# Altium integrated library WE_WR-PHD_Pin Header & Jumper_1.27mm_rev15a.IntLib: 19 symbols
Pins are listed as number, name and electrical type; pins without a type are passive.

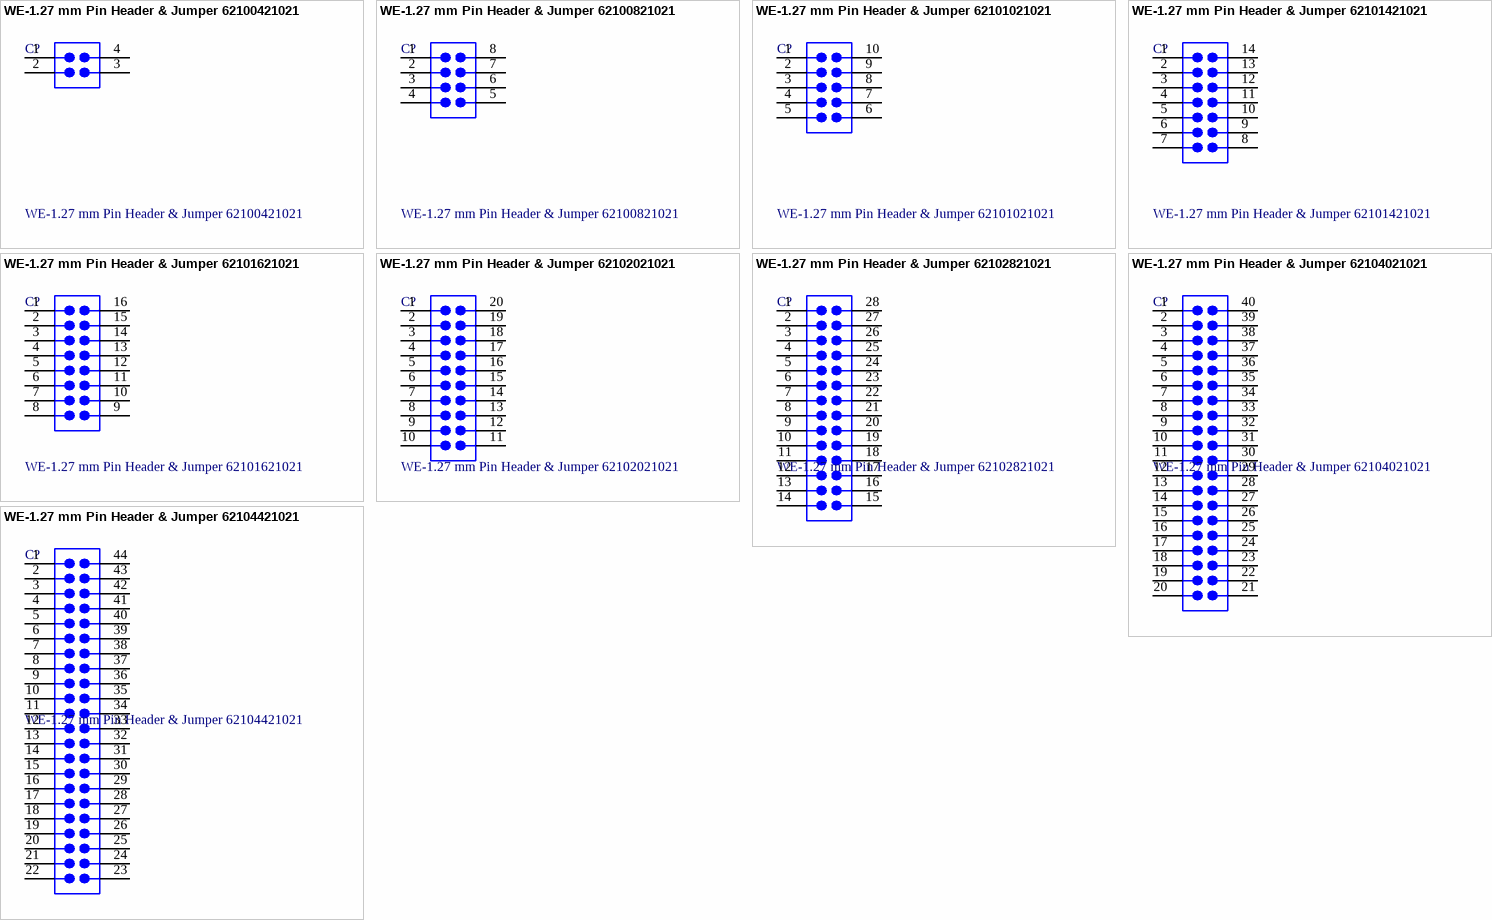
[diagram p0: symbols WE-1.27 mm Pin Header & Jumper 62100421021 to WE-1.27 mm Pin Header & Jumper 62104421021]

## WE-1.27 mm Pin Header & Jumper 62100421021
designator C?
WR-PHD 1.27 mm Dual SMT Pin Header; Manufacturer: Würth Elektronik eiSos GmbH; ComponentLink1 Description: Manufacturer; ComponentLink2 Description: Datasheet; NoPins: 04
footprint 62100421021 (4 pins, dual row, straight, gold plating)
pins: 1, 2, 3, 4

## WE-1.27 mm Pin Header & Jumper 62100821021
designator C?
WR-PHD 1.27 mm Dual SMT Pin Header; Manufacturer: Würth Elektronik eiSos GmbH; ComponentLink1 Description: Manufacturer; ComponentLink2 Description: Datasheet; NoPins: 08
footprint 62100821021 (8 pins, dual row, straight, gold plating)
pins: 1, 2, 3, 4, 5, 6, 7, 8

## WE-1.27 mm Pin Header & Jumper 62101021021
designator C?
WR-PHD 1.27 mm Dual SMT Pin Header; Manufacturer: Würth Elektronik eiSos GmbH; ComponentLink1 Description: Manufacturer; ComponentLink2 Description: Datasheet; NoPins: 10
footprint 62101021021 (10 pins, dual row, straight, gold plating)
pins: 1, 2, 3, 4, 5, 6, 7, 8, 9, 10

## WE-1.27 mm Pin Header & Jumper 62101421021
designator C?
WR-PHD 1.27 mm Dual SMT Pin Header; Manufacturer: Würth Elektronik eiSos GmbH; ComponentLink1 Description: Manufacturer; ComponentLink2 Description: Datasheet; NoPins: 14
footprint 62101421021 (14 pins, dual row, straight, gold plating)
pins: 1, 2, 3, 4, 5, 6, 7, 8, 9, 10, 11, 12, 13, 14

## WE-1.27 mm Pin Header & Jumper 62101621021
designator C?
WR-PHD 1.27 mm Dual SMT Pin Header; Manufacturer: Würth Elektronik eiSos GmbH; ComponentLink1 Description: Manufacturer; ComponentLink2 Description: Datasheet; NoPins: 16
footprint 62101621021 (16 pins, dual row, straight, gold plating)
pins: 1, 2, 3, 4, 5, 6, 7, 8, 9, 10, 11, 12, 13, 14, 15, 16

## WE-1.27 mm Pin Header & Jumper 62102021021
designator C?
WR-PHD 1.27 mm Dual SMT Pin Header; Manufacturer: Würth Elektronik eiSos GmbH; ComponentLink1 Description: Manufacturer; ComponentLink2 Description: Datasheet; NoPins: 20
footprint 62102021021 (20 pins, dual row, straight, gold plating)
pins: 1, 2, 3, 4, 5, 6, 7, 8, 9, 10, 11, 12, 13, 14, 15, 16, 17, 18, 19, 20

## WE-1.27 mm Pin Header & Jumper 62102821021
designator C?
WR-PHD 1.27 mm Dual SMT Pin Header; Manufacturer: Würth Elektronik eiSos GmbH; ComponentLink1 Description: Manufacturer; ComponentLink2 Description: Datasheet; NoPins: 28
footprint 62102821021 (28 pins, dual row, straight, gold plating)
pins: 1, 2, 3, 4, 5, 6, 7, 8, 9, 10, 11, 12, 13, 14, 15, 16, 17, 18, 19, 20, 21, 22, 23, 24, 25, 26, 27, 28

## WE-1.27 mm Pin Header & Jumper 62104021021
designator C?
WR-PHD 1.27 mm Dual SMT Pin Header; Manufacturer: Würth Elektronik eiSos GmbH; ComponentLink1 Description: Manufacturer; ComponentLink2 Description: Datasheet; NoPins: 40
footprint 62104021021 (40 pins, dual row, straight, gold plating)
pins: 1, 2, 3, 4, 5, 6, 7, 8, 9, 10, 11, 12, 13, 14, 15, 16, 17, 18, 19, 20, 21, 22, 23, 24, 25, 26, 27, 28, 29, 30, 31, 32, 33, 34, 35, 36, 37, 38, 39, 40

## WE-1.27 mm Pin Header & Jumper 62104421021
designator C?
WR-PHD 1.27 mm Dual SMT Pin Header; Manufacturer: Würth Elektronik eiSos GmbH; ComponentLink1 Description: Manufacturer; ComponentLink2 Description: Datasheet; NoPins: 44
footprint 62104421021 (44 pins, dual row, straight, gold plating)
pins: 1, 2, 3, 4, 5, 6, 7, 8, 9, 10, 11, 12, 13, 14, 15, 16, 17, 18, 19, 20, 21, 22, 23, 24, 25, 26, 27, 28, 29, 30, 31, 32, 33, 34, 35, 36, 37, 38, 39, 40, 41, 42, 43, 44


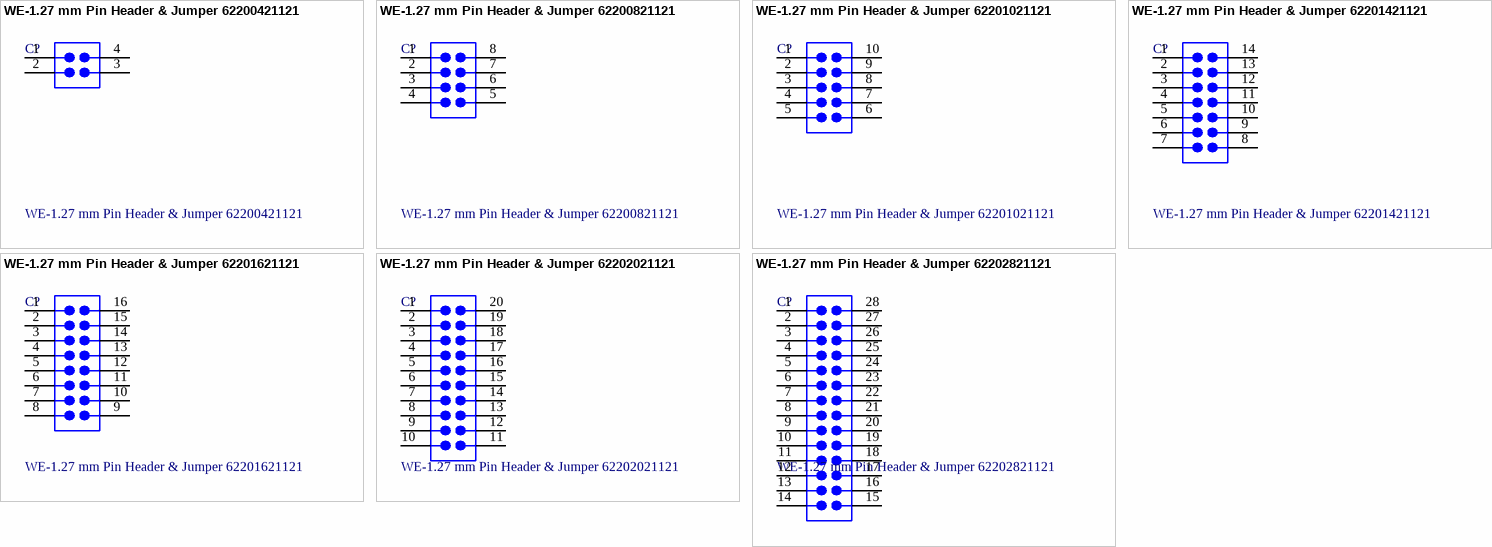
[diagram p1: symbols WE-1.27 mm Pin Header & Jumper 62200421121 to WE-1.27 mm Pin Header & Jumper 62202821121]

## WE-1.27 mm Pin Header & Jumper 62200421121
designator C?
WR-PHD 1.27 mm Dual Pin Header; Manufacturer: Würth Elektronik eiSos GmbH; ComponentLink1 Description: Manufacturer; ComponentLink2 Description: Datasheet; NoPins: 04
footprint 62200421121 (4 pins, dual row, straight, gold plating)
pins: 1, 2, 3, 4

## WE-1.27 mm Pin Header & Jumper 62200821121
designator C?
WR-PHD 1.27 mm Dual Pin Header; Manufacturer: Würth Elektronik eiSos GmbH; ComponentLink1 Description: Manufacturer; ComponentLink2 Description: Datasheet; NoPins: 08
footprint 62200821121 (8 pins, dual row, straight, gold plating)
pins: 1, 2, 3, 4, 5, 6, 7, 8

## WE-1.27 mm Pin Header & Jumper 62201021121
designator C?
WR-PHD 1.27 mm Dual Pin Header; Manufacturer: Würth Elektronik eiSos GmbH; ComponentLink1 Description: Manufacturer; ComponentLink2 Description: Datasheet; NoPins: 10
footprint 62201021121 (10 pins, dual row, straight, gold plating)
pins: 1, 2, 3, 4, 5, 6, 7, 8, 9, 10

## WE-1.27 mm Pin Header & Jumper 62201421121
designator C?
WR-PHD 1.27 mm Dual Pin Header; Manufacturer: Würth Elektronik eiSos GmbH; ComponentLink1 Description: Manufacturer; ComponentLink2 Description: Datasheet; NoPins: 10
footprint 62201421121 (14 pins, dual row, straight, gold plating)
pins: 1, 2, 3, 4, 5, 6, 7, 8, 9, 10, 11, 12, 13, 14

## WE-1.27 mm Pin Header & Jumper 62201621121
designator C?
WR-PHD 1.27 mm Dual Pin Header; Manufacturer: Würth Elektronik eiSos GmbH; ComponentLink1 Description: Manufacturer; ComponentLink2 Description: Datasheet; NoPins: 16
footprint 62201621121 (16 pins, dual row, straight, gold plating)
pins: 1, 2, 3, 4, 5, 6, 7, 8, 9, 10, 11, 12, 13, 14, 15, 16

## WE-1.27 mm Pin Header & Jumper 62202021121
designator C?
WR-PHD 1.27 mm Dual Pin Header; Manufacturer: Würth Elektronik eiSos GmbH; ComponentLink1 Description: Manufacturer; ComponentLink2 Description: Datasheet; NoPins: 20
footprint 62202021121 (20 pins, dual row, straight, gold plating)
pins: 1, 2, 3, 4, 5, 6, 7, 8, 9, 10, 11, 12, 13, 14, 15, 16, 17, 18, 19, 20

## WE-1.27 mm Pin Header & Jumper 62202821121
designator C?
WR-PHD 1.27 mm Dual Pin Header; Manufacturer: Würth Elektronik eiSos GmbH; ComponentLink1 Description: Manufacturer; ComponentLink2 Description: Datasheet; NoPins: 28
footprint 62202821121 (28 pins, dual row, straight, gold plating)
pins: 1, 2, 3, 4, 5, 6, 7, 8, 9, 10, 11, 12, 13, 14, 15, 16, 17, 18, 19, 20, 21, 22, 23, 24, 25, 26, 27, 28


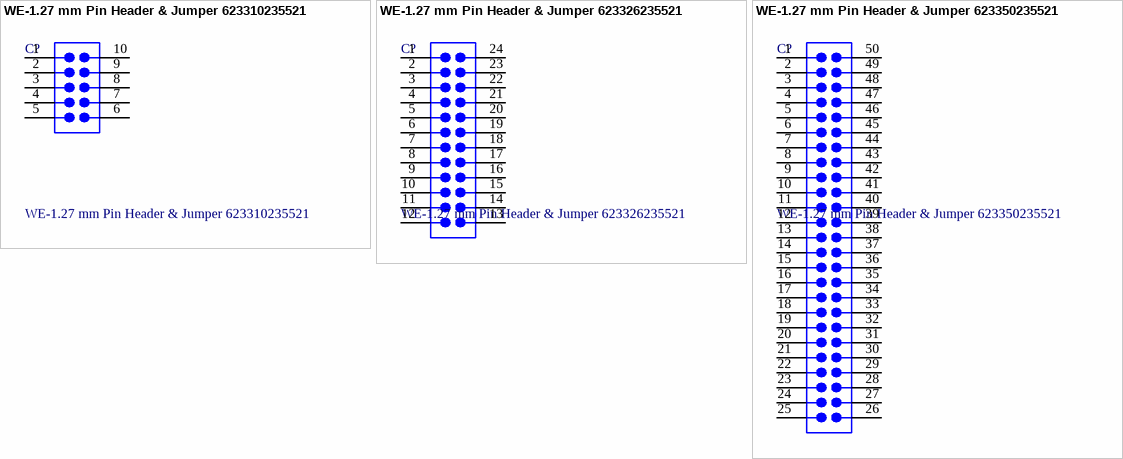
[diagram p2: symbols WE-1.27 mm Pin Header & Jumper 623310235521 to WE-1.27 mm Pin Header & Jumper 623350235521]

## WE-1.27 mm Pin Header & Jumper 623310235521
designator C?
WR-PHD 1.27 mm Dual SMT Pin Header H=1.80mm; Manufacturer: Würth Elektronik eiSos GmbH; ComponentLink1 Description: Manufacturer; ComponentLink2 Description: Datasheet; NoPins: 10
footprint 623310235521 (10 pins, dual row, straight, gold plating)
pins: 1, 2, 3, 4, 5, 6, 7, 8, 9, 10

## WE-1.27 mm Pin Header & Jumper 623326235521
designator C?
WR-PHD 1.27 mm Dual SMT Pin Header H=1.80mm; Manufacturer: Würth Elektronik eiSos GmbH; ComponentLink1 Description: Manufacturer; ComponentLink2 Description: Datasheet; NoPins: 26
footprint 623326235521 (26 pins, dual row, straight, gold plating)
pins: 1, 2, 3, 4, 5, 6, 7, 8, 9, 10, 11, 12, 13, 14, 15, 16, 17, 18, 19, 20, 21, 22, 23, 24

## WE-1.27 mm Pin Header & Jumper 623350235521
designator C?
WR-PHD 1.27 mm Dual SMT Pin Header H=1.80mm; Manufacturer: Würth Elektronik eiSos GmbH; ComponentLink1 Description: Manufacturer; ComponentLink2 Description: Datasheet; NoPins: 50
footprint 623350235521 (50 pins, dual row, straight, gold plating)
pins: 1, 2, 3, 4, 5, 6, 7, 8, 9, 10, 11, 12, 13, 14, 15, 16, 17, 18, 19, 20, 21, 22, 23, 24, 25, 26, 27, 28, 29, 30, 31, 32, 33, 34, 35, 36, 37, 38, 39, 40, 41, 42, 43, 44, 45, 46, 47, 48, 49, 50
